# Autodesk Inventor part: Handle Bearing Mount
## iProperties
Created: 2005-03
Part Number: Handle Bearing Mount
Document SubType Name: Modeling
Designer: Admin
Material: Cast Iron
Density: 7.25 g/cm^3
Author: Admin
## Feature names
1. Extrusion1
2. Extrusion2
3. Extrusion3
4. Hole1
5. Extrusion4
6. Hole2
7. Chamfer1
8. Fillet1
